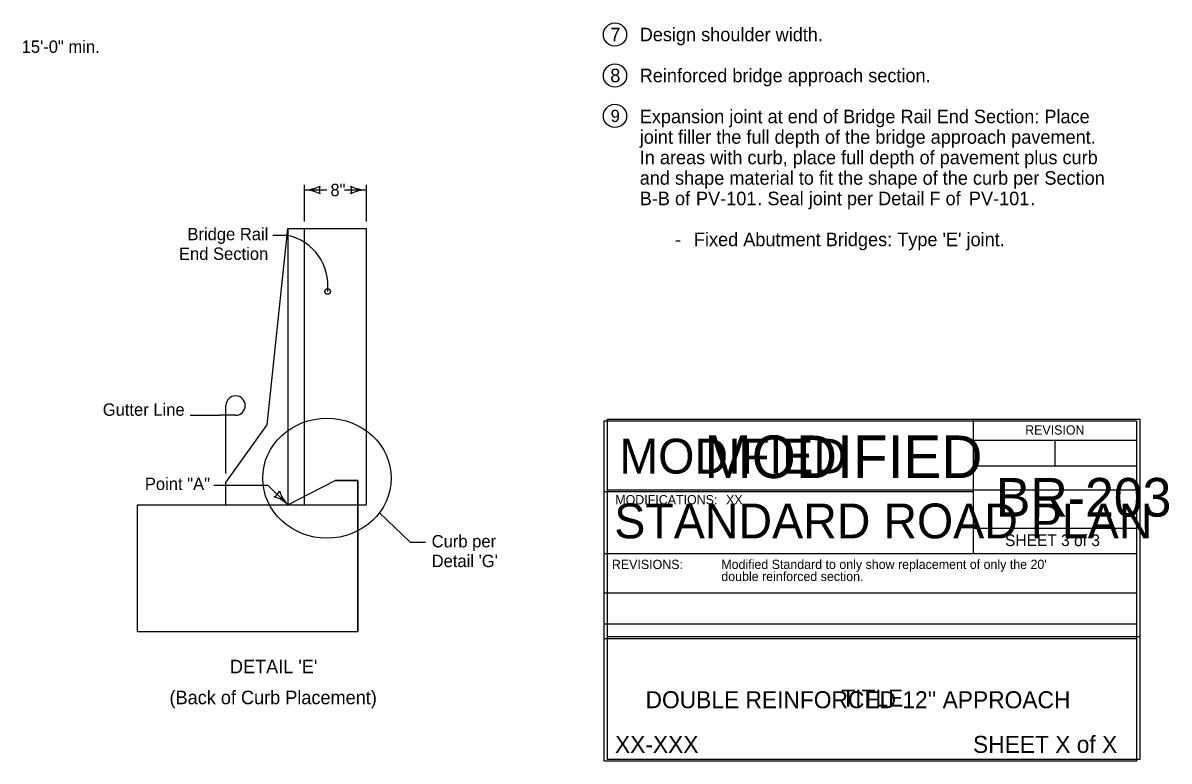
# Model space of a CAD drawing. Extents: x -2135039 to -2124495, y -2139046 to -2132546.
# Drawn here: x -2126039 to -2124557, y -2139046 to -2138091 of the extents above; entities that cross this region are included whole.
import ezdxf

# ---------------------------------------------------------------- set-up
doc = ezdxf.new("R2010")
doc.units = 0
for name, color, linetype in [('Barrier', 7, 'Continuous'), ('BridgeSuperStructureExisting', 7, 'Continuous'), ('Dimension', 7, 'Continuous'), ('dsnAlignmentCurveData', 7, 'Continuous'), ('dsnAlignmentTic', 7, 'Continuous'), ('dsnCellElements', 7, 'Continuous'), ('DsnShtInsideBorder', 7, 'Continuous'), ('dsnStdLabel', 7, 'Continuous'), ('TC_Barrier', 7, 'Continuous')]:
    doc.layers.add(name, color=color, linetype=linetype)

msp = doc.modelspace()

# ---------------------------------------------------------------- linework, layer by layer
at = {"layer": 'BridgeSuperStructureExisting'}
for p, q in [((-2125674.7, -2138348), (-2125674.7, -2138300.7)), ((-2125594.7, -2138348), (-2125594.7, -2138300.7)), ((-2125675, -2138307.4), (-2125645.9, -2138307.4)), ((-2125623, -2138307.4), (-2125594.7, -2138307.4)), ((-2125723, -2138611.1), (-2125696.3, -2138357.1)), ((-2125696.3, -2138357.1), (-2125595, -2138357.1)), ((-2125696.3, -2138357.1), (-2125696.3, -2138714.7)), ((-2125675, -2138357.1), (-2125675, -2138703.7)), ((-2125595, -2138357.1), (-2125595, -2138714.7)), ((-2125696, -2138366.3), (-2125715.5, -2138366.3)), ((-2125822.7, -2138598.7), (-2125783.8, -2138598.7)), ((-2125776.3, -2138674), (-2125776.3, -2138606.2)), ((-2125776.3, -2138685.7), (-2125723, -2138611.1)), ((-2125595, -2138651.5), (-2125595, -2138683.1)), ((-2125776.3, -2138714.7), (-2125776.3, -2138685.7)), ((-2125606, -2138683.1), (-2125635, -2138683.1)), ((-2125635, -2138683.1), (-2125606, -2138683.1)), ((-2125606, -2138878.9), (-2125606, -2138683.1)), ((-2125606, -2138683.1), (-2125606, -2138878.9)), ((-2125721.6, -2138689.4), (-2125791.9, -2138689.4)), ((-2125721.6, -2138689.4), (-2125696.3, -2138714.7)), ((-2125696.3, -2138714.7), (-2125606, -2138714.7)), ((-2125675, -2138703.7), (-2125675, -2138714.7)), ((-2125606, -2138714.7), (-2125595, -2138714.7)), ((-2125578, -2138725.1), (-2125538, -2138762.7)), ((-2125538, -2138762.7), (-2125518.2, -2138762.7))]:
    msp.add_line(p, q, dxfattribs=at)
for points in [[(-2125696.3, -2138714.7), (-2125635, -2138683.1)], [(-2125696.3, -2138714.7), (-2125635, -2138683.1)], [(-2125606, -2138878.9), (-2125890.4, -2138878.9), (-2125890.4, -2138714.7), (-2125744.3, -2138714.7), (-2125696.3, -2138714.7)], [(-2125606, -2138878.9), (-2125890.4, -2138878.9), (-2125890.4, -2138714.7), (-2125744.3, -2138714.7), (-2125696.3, -2138714.7)]]:
    msp.add_lwpolyline(points, dxfattribs=at)
for centre in [(-2125273.5, -2138106.4), (-2125273.5, -2138159.4), (-2125273.5, -2138211.6)]:
    msp.add_circle(centre, 15, dxfattribs=at)
msp.add_arc((-2125711.1, -2138431.2), 66.7, 353.5756, 76.8823, dxfattribs=at)
msp.add_ellipse((-2125645.7, -2138680.1), major_axis=(83, 0), ratio=0.93542, dxfattribs=at)
at = {"layer": 'Dimension'}
for p, q in [((-2124810.4, -2138605.9), (-2124810.4, -2138697.3)), ((-2124810.4, -2138630.9), (-2124599.4, -2138630.9)), ((-2124704.9, -2138630.9), (-2124704.9, -2138664.1)), ((-2124810.4, -2138664.1), (-2124599.4, -2138664.1)), ((-2125287.5, -2138697.3), (-2124810.4, -2138697.3)), ((-2124810.4, -2138697.3), (-2124810.4, -2138777.3)), ((-2124599.4, -2138745.1), (-2124810.4, -2138745.1)), ((-2125287.5, -2138777.3), (-2124599.4, -2138777.3)), ((-2125287.5, -2138828.3), (-2124599.4, -2138828.3)), ((-2125287.5, -2138868.3), (-2124599.4, -2138868.3)), ((-2125287.5, -2138887.3), (-2124599.4, -2138887.3))]:
    msp.add_line(p, q, dxfattribs=at)
msp.add_lwpolyline([(-2125287.5, -2138605.9), (-2124599.4, -2138605.9), (-2124599.4, -2139045.9), (-2125287.5, -2139045.9)], close=True, dxfattribs=at)
msp.add_lwpolyline([(-2125287.5, -2138605.9), (-2124599.4, -2138605.9), (-2124599.4, -2139045.9), (-2125287.5, -2139045.9)], close=True, dxfattribs=at)
at = {"layer": 'dsnCellElements'}
for centre, radius, start, end in [((-2125675, -2138264.9), 42.5, 270, 298.0725), ((-2125675, -2138349.9), 42.5, 61.9275, 90), ((-2125639.3, -2138307.4), 16.4, 162.2666, 197.7334), ((-2125630.3, -2138307.4), 16.4, 342.2666, 17.7333), ((-2125594.7, -2138264.9), 42.5, 241.9275, 270), ((-2125594.7, -2138349.9), 42.5, 90, 118.0725), ((-2125721.5, -2138689.5), 16.4, 297.2666, 332.7333), ((-2125666.2, -2138684.6), 42.5, 196.9275, 225), ((-2125726.3, -2138744.7), 42.5, 45, 73.0725)]:
    msp.add_arc(centre, radius, start, end, dxfattribs=at)
at = {"layer": 'DsnShtInsideBorder'}
for p, q in [((-2125283.1, -2138695), (-2124595.1, -2138695)), ((-2125283.1, -2138885), (-2124595.1, -2138885))]:
    msp.add_line(p, q, dxfattribs=at)
msp.add_lwpolyline([(-2125283.1, -2138603.7), (-2124595.1, -2138603.7), (-2124595.1, -2139043.7), (-2125283.1, -2139043.7)], close=True, dxfattribs=at)
at = {"layer": 'TC_Barrier'}
for p, q in [((-2125776.3, -2138606.2), (-2125776.3, -2138586.2)), ((-2125763.8, -2138598.7), (-2125783.8, -2138598.7))]:
    msp.add_line(p, q, dxfattribs=at)
msp.add_circle((-2125644.9, -2138438.7), 3.54, dxfattribs=at)
msp.add_arc((-2125763.8, -2138586.2), 12.5, 270, 180, dxfattribs=at)

# ---------------------------------------------------------------- texts
at = {"layer": 'Barrier'}
for s, height, p in [('7', 17.5, (-2125279.5, -2138115.1)), ('Design shoulder width.', 17.5, (-2125241.5, -2138115.1)), ('8', 17.5, (-2125279.6, -2138168.1)), ('Reinforced bridge approach section.', 17.5, (-2125241.5, -2138168.1)), ('9', 16, (-2125279.1, -2138219.6)), ('Expansion joint at end of Bridge Rail End Section: Place', 17.5, (-2125241.5, -2138221.1)), ('joint filler the full depth of the bridge approach pavement.', 17.5, (-2125241.5, -2138247.6)), ('In areas with curb, place full depth of pavement plus curb', 17.5, (-2125241.5, -2138274.1)), ('and shape material to fit the shape of the curb per Section', 17.5, (-2125241.5, -2138300.6)), ('B-B of ', 17.5, (-2125241.5, -2138327.1)), ('PV-101', 17.5, (-2125168.8, -2138327.1)), ('PV-101', 17.5, (-2125168.8, -2138327.1)), ('. Seal joint per Detail F of ', 17.5, (-2125089.5, -2138327.1)), ('PV-101', 17.5, (-2124816.1, -2138327.1)), ('PV-101', 17.5, (-2124816.1, -2138327.1)), ('.', 17.5, (-2124736.8, -2138327.1)), ('       -', 17.5, (-2125241.5, -2138380.1)), ("Fixed Abutment Bridges: Type 'E' joint.", 17.5, (-2125171.5, -2138380.1))]:
    msp.add_text(s, height=height, dxfattribs=at).set_placement(p)
at = {"layer": 'BridgeSuperStructureExisting'}
for s, height, p in [('8"', 16, (-2125641.3, -2138315.4)), ('Bridge Rail ', 16, (-2125826.1, -2138372.4)), ('End Section', 16, (-2125837, -2138397.8)), ('Gutter Line', 16, (-2125935.5, -2138599.4)), ('Point "A"', 16, (-2125881.1, -2138695.4)), ('Curb per', 16, (-2125510.4, -2138769.6)), ("Detail 'G'", 16, (-2125510.4, -2138795.1)), ("DETAIL 'E'", 17.5, (-2125771.1, -2138932.4))]:
    msp.add_text(s, height=height, dxfattribs=at).set_placement(p)
at = {"layer": 'Dimension'}
for s, height, p in [('REVISION', 12, (-2124743.4, -2138623.8)), ('BR-203', 50, (-2124781.2, -2138729.8)), ('STANDARD ROAD PLAN', 45.001, (-2125274.4, -2138757.9)), ('SHEET 3 of 3', 15, (-2124769.4, -2138767.9)), ("Modified Standard to only show replacement of only the 20' ", 12, (-2125136.1, -2138797.5)), ('double reinforced section.', 12, (-2125136.1, -2138813.1)), ("DOUBLE REINFORCED 12'' APPROACH", 22, (-2125234, -2138977.6))]:
    msp.add_text(s, height=height, dxfattribs=at).set_placement(p)
at = {"layer": 'dsnAlignmentCurveData'}
msp.add_text('REVISIONS:', height=12, dxfattribs=at).set_placement((-2125277.5, -2138797.6))
at = {"layer": 'dsnAlignmentTic'}
msp.add_text('MODIFIED', height=45, dxfattribs=at).set_placement((-2125267.8, -2138674.1))
at = {"layer": 'DsnShtInsideBorder'}
for s, height, p in [('MODIFIED', 55, (-2125158.1, -2138679.9)), ('MODIFICATIONS:', 12, (-2125273.1, -2138713.9)), ('XX', 12, (-2125129.9, -2138713.9)), ('TITLE', 22, (-2124981.1, -2138975.4)), ('SHEET X of X', 22, (-2124810.8, -2139035.3)), ('XX-XXX', 22, (-2125273.5, -2139035.3))]:
    msp.add_text(s, height=height, dxfattribs=at).set_placement(p)
at = {"layer": 'dsnStdLabel'}
for s, height, p in [('15\'-0" min.', 16, (-2126040.3, -2138130.1)), ('(Back of Curb Placement)', 17.5, (-2125849.2, -2138972.4))]:
    msp.add_text(s, height=height, dxfattribs=at).set_placement(p)

doc.saveas('drawing.dxf')
